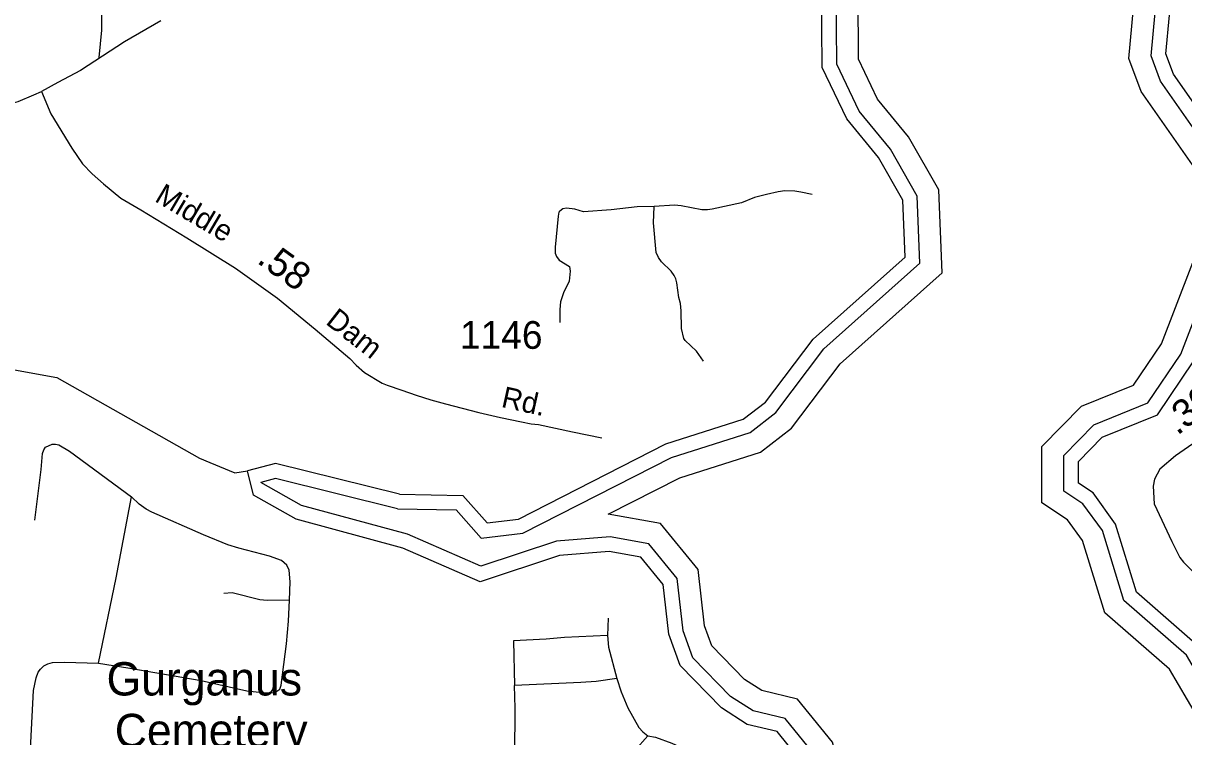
# Model space of a CAD drawing. Extents: x 2104537 to 2336408, y 34176 to 229611.
# Drawn here: x 2187970 to 2193201, y 68278 to 71492 of the extents above; entities that cross this region are included whole.
import ezdxf

# ---------------------------------------------------------------- set-up
doc = ezdxf.new("R2010")
doc.units = 0
for name, color, linetype in [('Exist Cultural Cemetery Label', 7, 'Continuous'), ('Exist Hydrographic Buffer Line', 7, 'Continuous'), ('Exist Hydrographic Creek Single Shore', 7, 'Continuous'), ('Exist Hydrographic River Shore', 7, 'Continuous'), ('Exist Road Non-System Type 51', 7, 'Continuous'), ('Exist Road Secondary Mileage Hundredths English Label', 7, 'Continuous'), ('Exist Road Secondary Type 51 Attributed', 7, 'Continuous'), ('Exist Road Secondary Type 51 Label', 7, 'Continuous'), ('Exist Road Secondary Type 51 Number Label', 7, 'Continuous')]:
    doc.layers.add(name, color=color, linetype=linetype)

msp = doc.modelspace()

# ---------------------------------------------------------------- linework, layer by layer
at = {"layer": 'Exist Hydrographic Buffer Line'}
for points in [[(2189657.1, 69305), (2189921.4, 69299.9), (2190034.2, 69172.2), (2190222.1, 69194.6), (2190891.7, 69535.7), (2191246.5, 69649), (2191362.8, 69738.2), (2191579.1, 70024.7), (2192011.4, 70410.4), (2191999.5, 70713.4), (2191878.9, 70924.6), (2191737.4, 71096.1), (2191637.1, 71307.4), (2191634.3, 71644.6), (2191706.1, 71787.8), (2192021.6, 72128), (2192139.2, 72410.5), (2192118.4, 72679.1), (2191931, 73155.5), (2191874.6, 73444.1)], [(2190607, 69280.2), (2190929.3, 69444.4), (2191292.8, 69560.4), (2191433.3, 69668.2), (2191651.9, 69957.7), (2192111.6, 70367.8), (2192096.9, 70741.3), (2191960.2, 70980.8), (2191821, 71149.3), (2191735.4, 71329.9), (2191732.9, 71621.7), (2191787.8, 71731.2), (2192105.7, 72073.9), (2192239.2, 72394.5), (2192215.4, 72701.4), (2192164, 72832.1)], [(2193346.9, 68149.6), (2193298.6, 68305.6), (2193136.8, 68581.4), (2192844.6, 68836.2), (2192744.7, 69162), (2192677.5, 69255.2), (2192561.6, 69331.1), (2192561.6, 69585), (2192739.6, 69767), (2192974.9, 69861.3), (2193100.3, 70047), (2193304.3, 70577), (2193303.1, 70763.9), (2193008.1, 71185.1), (2192953.9, 71332.4), (2192974.8, 71560), (2193133.8, 72074.7), (2193218.8, 72204), (2193354.4, 72275.5), (2193737.4, 72293.8)], [(2193439.2, 68184.2), (2193389.3, 68345.6), (2193213.6, 68645.1), (2192930.5, 68891.9), (2192834.1, 69206.4), (2192746.6, 69327.5), (2192660.1, 69384.2), (2192660.1, 69544.9), (2192795.5, 69683.3), (2193039.6, 69781.2), (2193188.2, 70001.2), (2193402.9, 70559.1), (2193401.3, 70795.3), (2193096, 71231.1), (2193053.9, 71345.5), (2193071.9, 71540.7), (2193223.7, 72032.3), (2193287.1, 72128.7), (2193381, 72178.2), (2193769.4, 72196.7)], [(2189657.1, 69305), (2189107.2, 69441.4), (2189040.7, 69423.4)], [(2189702.4, 69189.6), (2189224.8, 69319.2), (2189040.7, 69423.4)], [(2191901.5, 67435.5), (2191790.1, 67814.1), (2191681, 68014.5), (2191617.1, 68253.7), (2191460, 68447.4), (2191298.6, 68486.1), (2191220.9, 68535.5), (2191074.1, 68686.8), (2191041.4, 68777.8), (2191012, 69030.4), (2190842.4, 69237.7), (2190607, 69280.2)], [(2191804.3, 67417), (2191698.7, 67776.3), (2191588.9, 67977.8), (2191527.5, 68208), (2191404.6, 68359.5), (2191259.7, 68394.2), (2191158.4, 68458.6), (2190988.6, 68633.5), (2190944.9, 68755.1), (2190917.5, 68990.4), (2190789.2, 69147.3), (2190614.8, 69178.8), (2190373.5, 69158.8), (2190032.8, 69046.4), (2189702.4, 69189.6)]]:
    msp.add_lwpolyline(points, dxfattribs=at)
at = {"layer": 'Exist Hydrographic Creek Single Shore'}
msp.add_lwpolyline([(2181851.6, 69094.7), (2181845.4, 68835.6), (2182037.5, 68635), (2182163.5, 68445.6), (2182330.6, 68386.6), (2182547.5, 68405.4), (2183304.6, 68676.2), (2183810.4, 68912.5), (2184093.6, 69080.9), (2184242.5, 69140.4), (2184583.5, 69291.3), (2184991.5, 69401.6), (2186689.6, 69769.1), (2187862.7, 69943.3), (2188121.6, 69895.7), (2188764.7, 69532.2), (2188810.8, 69513.1), (2188923.6, 69466.8), (2188981.6, 69475.5)], dxfattribs=at)
at = {"layer": 'Exist Hydrographic River Shore'}
for points in [[(2189665.7, 69370.4), (2189951.5, 69364.9), (2190060.6, 69241.4), (2190202.7, 69258.4), (2190866.7, 69596.6), (2191215.7, 69708), (2191315.7, 69784.8), (2191530.6, 70069.4), (2191944.6, 70438.7), (2191934.6, 70694.8), (2191824.7, 70887.2), (2191681.6, 71060.6), (2191571.7, 71292.3), (2191568.6, 71659.9), (2191651.6, 71825.6), (2191965.6, 72164), (2192072.6, 72421.1), (2192053.7, 72664.2), (2191867.7, 73137.1), (2191815.7, 73403.8)], [(2193500.8, 68207.2), (2193449.7, 68372.2), (2193264.8, 68687.5), (2192987.7, 68929.1), (2192893.6, 69236), (2192792.7, 69375.8), (2192725.7, 69419.7), (2192725.7, 69518.1), (2192832.7, 69627.6), (2193082.7, 69727.8), (2193246.7, 69970.6), (2193468.6, 70547.1), (2193466.7, 70816.2), (2193154.7, 71261.8), (2193120.6, 71354.3), (2193136.6, 71527.9), (2193283.6, 72004.1), (2193332.6, 72078.6), (2193398.7, 72113.4), (2193790.7, 72132.1)], [(2189665.7, 69370.4), (2189106.5, 69509.2), (2188981.6, 69475.5)], [(2189680.7, 69127.5), (2189199.6, 69258), (2189007.7, 69366.7), (2188981.6, 69475.5)], [(2191739.6, 67404.6), (2191637.7, 67751), (2191527.6, 67953.3), (2191467.7, 68177.5), (2191367.6, 68300.9), (2191233.7, 68333), (2191116.6, 68407.4), (2190931.7, 68598), (2190880.6, 68740), (2190854.6, 68963.7), (2190753.7, 69087), (2190611.6, 69112.7), (2190386.7, 69094), (2190029.7, 68976.3), (2189680.7, 69127.5)]]:
    msp.add_lwpolyline(points, dxfattribs=at)
at = {"layer": 'Exist Road Non-System Type 51'}
msp.add_line((2190606.4, 68811.6), (2190603.2, 68733.6), dxfattribs=at)
for points in [[(2188312.9, 71337.8), (2188324.8, 71459.9), (2188324.8, 71561.3), (2188321.2, 71595.8), (2188320.7, 71598.9)], [(2191525.7, 70719.7), (2191475.4, 70731.2), (2191447.3, 70734.7), (2191403.4, 70736.2), (2191372.4, 70732.2), (2191319.4, 70721.1), (2191265.6, 70706.3), (2191208.1, 70683.5), (2191074.7, 70653.9), (2191054.3, 70651.7), (2191028.4, 70651.2), (2190935.5, 70668.8), (2190905.4, 70672), (2190814.1, 70666.5)], [(2190814.1, 70666.5), (2190737.9, 70665.3), (2190620.2, 70651.9), (2190495, 70642.1), (2190456.2, 70654.1), (2190418.3, 70659.4), (2190402.1, 70655.1), (2190388.2, 70645.5), (2190384.5, 70641), (2190380.5, 70622.7), (2190368.3, 70482.5), (2190368.1, 70456.6), (2190373.7, 70441.4), (2190385.2, 70424.8), (2190431.6, 70395.3), (2190435.8, 70375.6), (2190431, 70330.4), (2190405, 70277.1), (2190391.4, 70237), (2190388.1, 70202.9), (2190388.9, 70144.1)], [(2191035.5, 69969.3), (2191004.6, 70014.9), (2190953.7, 70062.4), (2190948, 70072.4), (2190937.3, 70117.2), (2190936.2, 70196), (2190932, 70229.8), (2190924.6, 70256.2), (2190916, 70322.7), (2190911.1, 70340.5), (2190904.2, 70355.7), (2190889.8, 70375.3), (2190847.3, 70416.8), (2190832.9, 70436.8), (2190823.2, 70459.3), (2190811, 70592.4), (2190814.1, 70666.5)], [(2188022.7, 69253.5), (2188050.7, 69481.6), (2188056.4, 69553.7), (2188062.3, 69569.7), (2188070, 69581.6), (2188099.8, 69595.8), (2188115.9, 69596.2), (2188130.3, 69592.3), (2188178.3, 69564.8), (2188457.8, 69358.6)], [(2188309.1, 68608.5), (2188388.4, 68994.1), (2188457.8, 69358.6)], [(2189170.3, 68893.1), (2189172.5, 68976), (2189168, 69028.3), (2189158.5, 69050.1), (2189134, 69071.6), (2189079.9, 69091.3), (2188941.5, 69126.5), (2188892, 69142.9), (2188783.2, 69187.3), (2188550.3, 69289.2), (2188524, 69303.2), (2188491.9, 69325.1), (2188457.8, 69358.6)], [(2188309.1, 68608.5), (2188441.6, 68588.6), (2188771.9, 68531), (2188977.7, 68484.7), (2189061.8, 68475.2), (2189104.5, 68477.3), (2189126.4, 68491.7), (2189132.4, 68509.6), (2189157, 68695.8), (2189166.1, 68798), (2189170.3, 68893.1)], [(2189170.3, 68893.1), (2189069.5, 68891.4), (2189037.1, 68895), (2188911.1, 68926), (2188874.9, 68923.7)], [(2190603.2, 68733.6), (2190409.5, 68725.1), (2190327.3, 68717.9), (2190179.5, 68709.9), (2190184.2, 68508)], [(2190603.2, 68733.6), (2190607.8, 68681.6), (2190645.8, 68540.1)], [(2187973.5, 67777), (2187993.5, 68045.4), (2188016.4, 68485.5), (2188028, 68543.4), (2188038, 68568.1), (2188047.5, 68581.7), (2188063.5, 68597.8), (2188081.4, 68606.3), (2188101.5, 68611.5), (2188155.4, 68614.4), (2188309.1, 68608.5)], [(2190645.8, 68540.1), (2190552, 68526.9), (2190484, 68521.9), (2190184.2, 68508)], [(2190645.8, 68540.1), (2190664.6, 68480.4), (2190695.7, 68408.6), (2190744.9, 68319.4), (2190762.2, 68300.4), (2190785.5, 68281.9)], [(2190785.5, 68281.9), (2190726.1, 68215.1), (2190703.1, 68196.5), (2190676.6, 68182.6), (2190648.2, 68172), (2190541, 68144.5), (2190459.1, 68131.7), (2190215.4, 68118.6), (2190201.8, 68128.1), (2190190.9, 68144.4), (2190186.3, 68192), (2190187.8, 68406.3), (2190184.2, 68508)], [(2190785.5, 68281.9), (2190819.5, 68276.3), (2190893.8, 68249.3), (2190950, 68223.9), (2191026.9, 68193.9), (2191044.8, 68185.3), (2191073.8, 68161.5), (2191132.7, 68085.9), (2191170.8, 68033), (2191189.2, 68001.1), (2191217.9, 67943.5), (2191240.8, 67887.9), (2191291.9, 67796.4), (2191339.2, 67697), (2191398.6, 67583.7), (2191440.5, 67492), (2191462.3, 67450.6), (2191516.2, 67301.2), (2191541.7, 67193.5), (2191546.1, 67177.5)]]:
    msp.add_lwpolyline(points, dxfattribs=at)
at = {"layer": 'Exist Road Secondary Type 51 Attributed'}
for points in [[(2188590.1, 71503.1), (2188426, 71408.3), (2188227.5, 71279.1), (2188126.4, 71224.8), (2188053, 71185)], [(2184762.4, 70225.2), (2185148.6, 70408.2), (2185931.1, 70787.9), (2186241.8, 70936.2), (2186325.5, 70972.9), (2186379.4, 70993.5), (2186451.4, 71015.8), (2186515.3, 71030.3), (2186643, 71051.4), (2187075, 71081.5), (2187344.9, 71090.7), (2187764.5, 71109.5), (2187838.8, 71117.9), (2187897.4, 71127.6), (2187946.9, 71139.2), (2188017.8, 71169.3), (2188053, 71185)], [(2188053, 71185), (2188094.1, 71083.8), (2188188.6, 70928.4), (2188237.1, 70859.1), (2188281, 70812.8), (2188331.9, 70768.9), (2188410.4, 70704.2), (2188500.5, 70651), (2188707.6, 70525.5), (2188927.1, 70389.1), (2189116.6, 70252.7), (2189285.3, 70113.9), (2189442.5, 69982.2), (2189470, 69951.6), (2189507.7, 69918.7), (2189588.4, 69870.6), (2189610.5, 69861.5), (2189676.1, 69839.7), (2189741.7, 69816.6), (2189807.1, 69795.5), (2189873.4, 69778.1), (2190023.3, 69738.9), (2190121.4, 69716.4), (2190216.6, 69696.7), (2190259.1, 69687.4), (2190292.8, 69683.8), (2190446.3, 69652), (2190577.9, 69624)], [(2193864.6, 69476.7), (2193703.9, 69677.8), (2193548.5, 69837.3), (2193413.6, 69722.5), (2193280.8, 69623.8), (2193164, 69543.2), (2193093.5, 69482.8), (2193069.4, 69438.5)], [(2193069.4, 69438.5), (2193063.3, 69406.2), (2193067.4, 69327.6), (2193146.6, 69156.7), (2193183.6, 69085.2), (2193200, 69063.5), (2193252.6, 69011.4)]]:
    msp.add_lwpolyline(points, dxfattribs=at)

# ---------------------------------------------------------------- texts
at = {"layer": 'Exist Cultural Cemetery Label'}
for s, p in [('Gurganus', (2188345.7, 68463.7)), ('Cemetery', (2188382.6, 68230.9))]:
    msp.add_text(s, height=150, dxfattribs=at).set_placement(p)
at = {"layer": 'Exist Road Secondary Mileage Hundredths English Label'}
for s, rotation, p in [('.58', 324.2525, (2189018.5, 70415.7)), ('.30', 37.8736, (2193171.8, 69632.4))]:
    msp.add_text(s, height=125, rotation=rotation, dxfattribs=at).set_placement(p)
at = {"layer": 'Exist Road Secondary Type 51 Label'}
for s, rotation, p in [('Middle', 329.3756, (2188557.9, 70692.5)), ('Dam', 322.0026, (2189328.9, 70140.2)), ('Rd.', 347.5837, (2190120.6, 69764))]:
    msp.add_text(s, height=95, rotation=rotation, dxfattribs=at).set_placement(p)
at = {"layer": 'Exist Road Secondary Type 51 Number Label'}
msp.add_text('1146', height=125, dxfattribs=at).set_placement((2189938.7, 70025.2))

doc.saveas('drawing.dxf')
